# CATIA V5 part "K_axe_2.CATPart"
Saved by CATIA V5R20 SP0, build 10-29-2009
Part number: axe 2
Publications: "Droite.1", "Plan.21"
Bounding box of the stored display mesh (mm): x -20 to 20, y -20 to 20, z -158 to 158
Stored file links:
  G:\Khaled_CFAO_2011\ST2M\ST2M_GR1\mponsin\Khaled\CAD_ThinkMOTION\K_axe_2.CATPart
  C:\Users\Socar\Documents\thinkmotion\Final\Diff2.CATProduct
  G:\Khaled_CFAO_2011\ST2M\ST2M_GR1\mponsin\Khaled\CAD_ThinkMOTION\K_mponsin.CATProduct
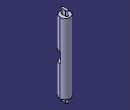
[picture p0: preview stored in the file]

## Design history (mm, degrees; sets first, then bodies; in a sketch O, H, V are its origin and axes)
External parameters (linked from other documents)
  `External.D axe` = 40 mm
  `External.R interne` = 160 mm
Set1
  DatumPoint1 to DatumPoint6: linked copy from another document
  Point1 "Origine": linked copy from another document
  Line1 "axe general": linked copy from another document
  Plane1: linked copy from another document
Set2
  Line2: type PtDir, RefPoint Point1, Direction xy-plane, Start 0, End 20
  Plane2: type 1Curve, Element1 edge [face of Pocket2 from Sketch3.A1 | end face of Pad1]
Body1 (main body)
  Sketch1 on xy-plane, origin (0, 0, 0), H (1, 0, 0), V (0, 1, 0)
    circle A1 centre (0, 0) radius 20
    radius A1 = 20 {= `External.D axe` /2}
  Pad1: profile Sketch1, direction (0, 0, 1), length 158 {= `External.R interne` -2mm}, opposite side length 158 {= `External.R interne` -2mm}
  Sketch2 on yz-plane, origin (0, 0, 0), H (0, 1, 0), V (0, 0, 1)
    line L1 (-24, 21) -> (1, 21)
    line L2 (1, 21) -> (1, -21)
    line L3 (1, -21) -> (-24, -21)
    line L4 (-24, -21) -> (-24, 21)
    distance L2 V = 1
    length L4 = 42 {= `External.D axe` +2mm}
    length L3 = 25 {= 5mm+`External.D axe` /2}
    horizontal: L1 H, L3 H
    vertical: L2 V, L4 V
    symmetry: L3 L1 H
  Pocket1: profile Sketch2, direction (-1, 0, 0), through (limit type 6), opposite side through (limit type 6)
  Sketch3 on end face of Pad1, origin (0, 0, 158), H (1, 0, 0), V (0, 1, 0)
    line L1 (-5, 7.5) -> (-5, -7.5)
    point P1 (-5, 7.5)
    point P2 (-5, -7.5)
    reference projected point E1 (-5, 7.5) from vertex of DatumPoint6
    reference projected point E2 (-5, -7.5) from vertex of DatumPoint3
    point P3 (5, -7.5)
    point P4 (5, 7.5)
    line L2 (5, 7.5) -> (5, -7.5)
    arc A1 centre (0, -7.5) radius 5 from (-5, -7.5) to (5, -7.5) ccw
    point P5 (0, -7.5)
    point P6 (-5, -7.5)
    point P7 (5, -7.5)
    reference projected point E3 (0, -7.5) from vertex of DatumPoint2
    reference projected point E4 (-5, -7.5) from vertex of DatumPoint3
    reference projected point E5 (5, -7.5) from vertex of DatumPoint1
    point P8 (5, 7.5)
    point P9 (-5, 7.5)
    arc A2 centre (0, 7.5) radius 5 from (-5, 7.5) to (5, 7.5) cw
    circle A3 centre (0, 0) radius 23
    radius A3 = 23 {= 3mm+`External.D axe` /2}
    coincidence: P1 E1, E2 P2, P5 E3, P6 E4, P7 E5, P1 P9, P2 P6, P3 P7, P4 P8
    symmetry: P2 P3 V, P1 P4 V, L1 L2 V, P7 P8 H, P6 P9 H, A1 A2 H
  Pocket2: profile Sketch3, direction (0, 0, -1), up to Plane1
  CircPattern1: of Pocket2, instances 2, angular step 180, axis from Line1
